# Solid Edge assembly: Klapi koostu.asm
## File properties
Author: Türk
Template: Iso Assembly.asm
Last saved by: Türk
Revision: 1
Application: Solid Edge
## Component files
ts.par
Klapi vedru.par
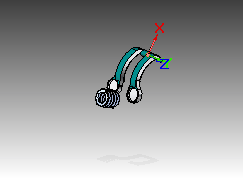
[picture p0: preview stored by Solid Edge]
